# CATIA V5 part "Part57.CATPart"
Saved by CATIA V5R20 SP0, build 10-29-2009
Part number: FA 042200-2
Revision: ANY
Definition: UNKNOWN
Nomenclature: FA 042200-2
Source: Unknown
Bounding box of the stored display mesh (mm): x -1.5 to 1.5, y 0 to 3.7, z -1.5 to 1.5
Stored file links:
  C:\Users\Utente\Desktop\IO LAVORO\3D X SITO CF\CUMSA\3D files FA\FA 042212-20\Part57.CATPart

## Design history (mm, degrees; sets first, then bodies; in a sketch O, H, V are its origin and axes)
Body1 "Cortar-Extruir1" (main body)
  Solid1: solid without history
